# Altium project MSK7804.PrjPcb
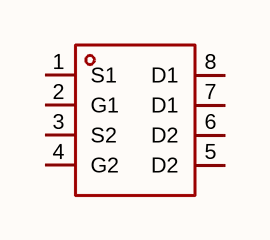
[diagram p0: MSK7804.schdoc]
1 sheet, 1 parts. Net scope: global (net labels, ports and power ports of the same name join across sheets).

## Sheet MSK7804.schdoc
size 127 x 101 mm

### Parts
Q?  msk7804  [DFN-8_L3.1-W3.2-P0.65-BL-EP]  (value not drawn)

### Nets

Not connected (* = marked no-connect by the designer): Q? 1(S1) 2(G1) 3(S2) 4(G2) 5(D2) 6(D2) 7(D1) 8(D1)

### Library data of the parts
Q? = msk7804: 数量:2个N沟道;漏源电压(Vdss):30V;连续漏极电流(Id):30A;导通电阻(RDS(on)):10mΩ@10V;耗散功率(Pd):1.5W;阈值电压(Vgs(th)):2.5V;; Manufacturer: MSKSEMI(美森科); AddInBom: yes; ModelId: 6511d791e00242de90c5f5fef9582459; ModelTransform: 118.11,125.984,0,0,0,0,0,0,0; Number: 2个N沟道; Drain to Source Voltage: 30V; Current - Continuous Drain(Id): 30A; Pd - Power Dissipation: 1.5W; Gate Threshold Voltage (Vgs(th)): 2.5V; Gate Charge(Qg): 9.63nC@4.5V; Input Capacitance(Ciss): 940pF; Reverse Transfer Capacitance (Crss@Vds): 109pF; Type: N沟道; Output Capacitance(Coss): 131pF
